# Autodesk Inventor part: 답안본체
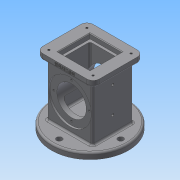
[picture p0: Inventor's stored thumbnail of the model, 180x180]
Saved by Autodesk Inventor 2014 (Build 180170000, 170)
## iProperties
Created: 2018-10
Part Number: 답안본체
Material: 일반
Document SubType Name: Modeling
Designer: NET
Density: 1 g/cm^3
Appearance: 기본값
Author: NET
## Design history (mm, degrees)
sketch "스케치1"
  geometry: L1 (-37, -33)-(37, -33); L2 (37, -33)-(37, 33); L3 (37, 33)-(-37, 33); L4 (-37, 33)-(-37, -33); L5 (-37, -33)-(37, 33); L6 (37, -33)-(-37, 33); 1 further point
  constraints: 12 end point, 2 midpoint, 2 parallel, 1 horizontal, 1 perpendicular
  dimensions: "d0" = 74 distance of L1.start L1.end; "d1" = 66 distance of L1.end L2.end
extrude "돌출1" new body sketch "스케치1" stored distance "d2" = 88; taper "d3" = 0 deg
sketch "스케치2"
  geometry: L1 (-46, -41)-(46, -41); L2 (46, -41)-(46, 41); L3 (46, 41)-(-46, 41); L4 (-46, 41)-(-46, -41); L5 (-46, -41)-(46, 41); L6 (46, -41)-(-46, 41); 1 further point
  constraints: 12 end point, 2 midpoint, 2 parallel, 1 horizontal, 1 perpendicular
  dimensions: "d4" = 82 distance of L1.end L2.end; "d5" = 92 distance of L2.end L3.end
extrude "돌출2" join sketch "스케치2" distance "d6" = 10; taper "d7" = 0 deg
sketch "스케치3"
  geometry: L1 (46, 41)-(46, -41) reference; C1 r 62.5 at (0, 0); 1 further point
  constraints: 1 centre point, 1 coincident
  dimensions: "d8" = 125 diameter of C1
extrude "돌출3" join sketch "스케치3" distance "d9" = 10; taper "d10" = 0 deg
sketch "스케치4"
  geometry: L1 (-26, -26)-(26, -26); L2 (26, -26)-(26, 26); L3 (26, 26)-(-26, 26); L4 (-26, 26)-(-26, -26); L5 (-26, -26)-(26, 26); L6 (26, -26)-(-26, 26); 1 further point
  constraints: 12 end point, 2 midpoint, 2 parallel, 2 perpendicular, 1 horizontal
  dimensions: "d11" = 52 distance of L1.end L2.end
extrude "돌출4" cut sketch "스케치4" distance "d12" = 8; taper "d13" = 0 deg
sketch "스케치5"
  geometry: L1 (-22, -22)-(22, -22); L2 (22, -22)-(22, 22); L3 (22, 22)-(-22, 22); L4 (-22, 22)-(-22, -22); L5 (-22, -22)-(22, 22); L6 (22, -22)-(-22, 22); 1 further point
  constraints: 12 end point, 2 midpoint, 2 parallel, 2 perpendicular, 1 horizontal
  dimensions: "d14" = 44 distance of L1.end L2.end
extrude "돌출5" cut sketch "스케치5" distance "d15" = 74; taper "d16" = 0 deg
sketch "스케치6"
  geometry: L1 (-25.5, -98)-(99.5, -98) reference; C1 r 35 at (37, -44); 1 further point
  constraints: 1 centre point, 1 coincident
  dimensions: "d17" = 70 diameter of C1; "d18" = 54 distance from line of L1 C1.centre
extrude "돌출6" cut sketch "스케치6" distance "d19" = 3; taper "d20" = 0 deg
hole "구멍1" diameter "d23" = 48; stored, may be unused: countersink angle "d27" = 90 deg, drill point angle "d29" = 118 deg; dims "d21" = 10, "d22" = 10, "d24" = 6, "d25" = 4, "d26" = 2, "d28" = 8
fillet "모깎기1" dims "d30" = 10
hole "구멍2" diameter "d33" = 3.242; stored, may be unused: countersink angle "d37" = 90 deg, drill point angle "d39" = 118 deg; dims "d31" = 10, "d32" = 10, "d34" = 4, "d35" = 4, "d36" = 2, "d38" = 6
hole "구멍3" diameter "d42" = 3.242; stored, may be unused: countersink angle "d46" = 90 deg, drill point angle "d48" = 118 deg; dims "d40" = 10, "d41" = 10, "d43" = 4, "d44" = 4, "d45" = 2, "d47" = 6
hole "구멍4" diameter "d51" = 3.242; stored, may be unused: countersink angle "d55" = 90 deg, drill point angle "d57" = 118 deg; dims "d49" = 10, "d50" = 10, "d52" = 4, "d53" = 4, "d54" = 2, "d56" = 6
hole "구멍5" diameter "d60" = 3.242; stored, may be unused: countersink angle "d64" = 90 deg, drill point angle "d66" = 118 deg; dims "d58" = 10, "d59" = 10, "d61" = 4, "d62" = 4, "d63" = 2, "d65" = 6
sketch "스케치7"
  geometry: C1 r 24 at (0, 0) reference; 1 further point
  constraints: 1 vertical alignment
  dimensions: "d67" = 29 distance of C1.centre point (0, 29)
hole "구멍6" sketch "스케치7" at (0, 29) diameter "d68" = 3.242; stored, may be unused: countersink angle "d72" = 90 deg, drill point angle "d74" = 118 deg; dims "d69" = 4, "d70" = 4, "d71" = 2, "d73" = 6
sketch "스케치8"
  geometry: L1 (-62.5, -54)-(62.5, -54) reference; L2 (0, -54)-(0, -36); L3 (0, -54)-(28, -54); L4 (28, -54)-(24.826, -36); L5 (24.826, -36)-(0, -36); 1 further point
  constraints: 8 end point, 1 midpoint, 1 parallel, 1 perpendicular, 1 point on line
  dimensions: "d78" = 18 distance of L2.start L2.end; "d79" = 28 distance of L2.start L3.end; "d80" = 80 deg angle of L1 L4
revolve "회전1" sketch "스케치8" stored, may be unused: angle "d81" = 90 deg
chamfer "모따기1" distance "d82" = 1; stored, may be unused: second distance "d83" = 2, angle "d84" = 45 deg
sketch "스케치9"
  geometry: C1 r 62.5 at (0, 0) reference; 1 further point
  constraints: 1 vertical alignment
  dimensions: "d85" = 50 distance of C1.centre point (0, 50)
hole "구멍7" sketch "스케치9" at (0, 50) diameter "d86" = 9; stored, may be unused: countersink angle "d90" = 90 deg, drill point angle "d92" = 118 deg; dims "d87" = 4, "d88" = 4, "d89" = 2, "d91" = 6
sketch "스케치10"
  geometry: L1 (98, -29.5)-(98, 95.5) reference; 3 further points
  constraints: 2 horizontal alignment
  dimensions: "d96" = 37 distance from line of L1 point (61, 33); "d97" = 43 distance of point (61, 33) point (18, 33)
hole "구멍8" sketch "스케치10" at (61, 33), (18, 33) diameter "d98" = 4.134; stored, may be unused: countersink angle "d102" = 90 deg, drill point angle "d104" = 118 deg; dims "d99" = 4, "d100" = 4, "d101" = 2, "d103" = 25.75
fillet "모깎기2" dims "d105" = 3
fillet "모깎기3" dims "d106" = 3
fillet "모깎기4" dims "d107" = 3
fillet "모깎기5" dims "d108" = 3
fillet "모깎기6" dims "d109" = 3
fillet "모깎기7" dims "d110" = 3
sketch "스케치11"
  geometry: 1 further point
sketch "스케치12"
  geometry: L1 (0, 0)-(72, 0) reference; L2 (-10, 0)-(-10, -7) reference; 2 further points
  constraints: 1 other
  dimensions: "d111" = 46 distance from line of point (36, -4) L2; "d112" = 4 distance from line of L1 point (36, -4)
feature "엠보싱1" sketch "스케치12" dims "d0" = 74, "d1" = 66, "d8" = 125, "d113" = 0.5, "d114" = 0
node "솔리드1"
mirror "대칭1"
pattern_circular "원형 패턴1" dims angle "d76" = 360 deg
mirror "대칭2"
pattern_circular "원형 패턴2" dims angle "d94" = 360 deg
